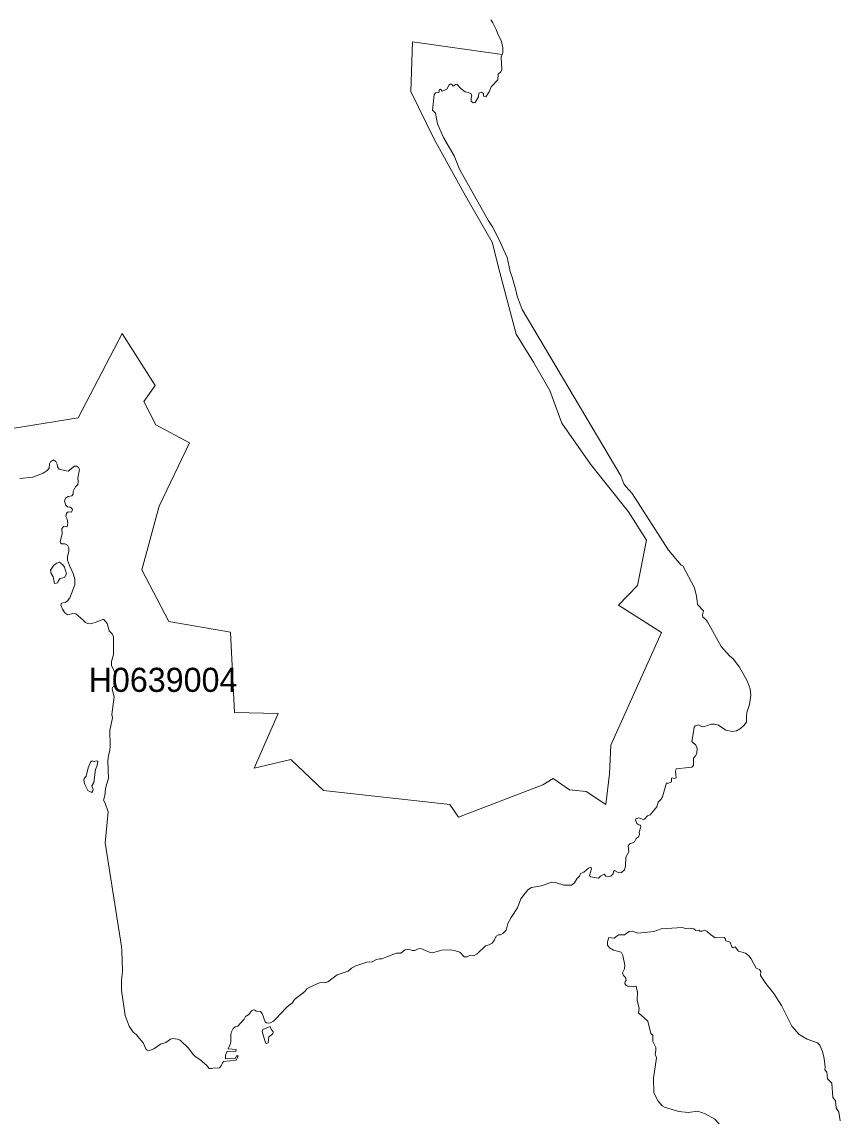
# Model space of a CAD drawing. Extents: x 369010 to 739155, y 6377141 to 6616555.
# Drawn here: x 443226 to 446619, y 6520707 to 6525263 of the extents above; entities that cross this region are included whole.
import ezdxf
from ezdxf.enums import TextEntityAlignment as Align

# ---------------------------------------------------------------- set-up
doc = ezdxf.new("R2010")
doc.units = 0
doc.header["$LTSCALE"] = 40
doc.layers.add('1', color=7, linetype='Continuous', lineweight=13)
doc.layers.add('2', color=7, linetype='Continuous')

msp = doc.modelspace()

# ---------------------------------------------------------------- linework, layer by layer
at = {"layer": '1'}
for points in [[(443133.32, 6523567.17), (443460.03, 6523619.97), (443641.92, 6523970.67), (443778.95, 6523754.36), (443731.62, 6523688.49), (443781.6, 6523591.01), (443921.29, 6523517.19), (443794.84, 6523253.38), (443723.68, 6522989.73), (443835.89, 6522775.57), (444091.59, 6522730.72), (444107.31, 6522398.38), (444289.2, 6522393.25), (444189.07, 6522166.35), (444341.83, 6522203.26), (444476.39, 6522074.16), (445000.87, 6522016.07), (445036.29, 6521963.77), (445386.83, 6522098.33), (445429.03, 6522124.64), (445497.55, 6522077.31), (445566.07, 6522069.36), (445647.66, 6522016.57), (445663.55, 6522143.18), (445668.84, 6522261.84), (445879.2, 6522730.05), (445700.12, 6522843.42), (445779.07, 6522925.18), (445815.98, 6523112.37), (445742.16, 6523231.04), (445584.11, 6523428.81), (445465.94, 6523598.95), (445415.95, 6523733.34), (445347.44, 6523852.01), (445276.27, 6523968.02), (445207.75, 6524223.89), (445176.14, 6524349.01), (445065.42, 6524541.5), (444936.16, 6524776.18), (444838.68, 6524973.96), (444846.46, 6525180.67), (445217.52, 6525128.04), (445220.16, 6525136.65), (445220.99, 6525155.18), (445214.7, 6525182.16), (445198.65, 6525216.75), (445192.69, 6525232.31), (445179.78, 6525259.12), (445171.01, 6525271.37)], [(444949.4, 6524840.07), (444940.96, 6524883.92), (444929.37, 6524897.16), (444935.66, 6524960.55), (444940.96, 6524968.83), (444955.19, 6524970.81), (444957.67, 6524982.56), (444961.98, 6524984.05), (444968.93, 6524975.28), (444978.2, 6524980.58), (444988.29, 6524984.05), (444998.55, 6525001.6), (445002.53, 6525004.91), (445007.32, 6525004.91), (445015.27, 6524996.63), (445024.54, 6525004.08), (445030.33, 6525004.41), (445046.88, 6524987.36), (445064.92, 6524973.3), (445077.66, 6524969.82), (445089.08, 6524964.52), (445092.06, 6524956.25), (445089.08, 6524946.48), (445090.08, 6524933.74), (445098.35, 6524927.45), (445106.13, 6524929.27), (445119.87, 6524951.78), (445120.86, 6524966.84), (445126.16, 6524970.32), (445132.45, 6524971.31), (445141.22, 6524965.52), (445141.22, 6524955.75), (445150.65, 6524951.78), (445163.73, 6524972.8), (445172, 6524993.32), (445199.81, 6525022.62), (445201.3, 6525046.95), (445213.05, 6525056.21), (445216.69, 6525065.98), (445214.2, 6525116.62), (445217.52, 6525128.04), (444846.46, 6525180.67), (444838.68, 6524973.96), (444936.16, 6524776.18), (445065.42, 6524541.5), (445176.14, 6524349.01), (445207.75, 6524223.89), (445276.27, 6523968.02), (445347.44, 6523852.01), (445415.95, 6523733.34), (445465.94, 6523598.95), (445584.11, 6523428.81), (445742.16, 6523231.04), (445815.98, 6523112.37), (445779.07, 6522925.18), (445700.12, 6522843.42), (445879.2, 6522730.05), (445668.84, 6522261.84), (445663.55, 6522143.18), (445647.66, 6522016.57), (445566.07, 6522069.36), (445497.55, 6522077.31), (445429.03, 6522124.64), (445386.83, 6522098.33), (445036.29, 6521963.77), (445000.87, 6522016.07), (444476.39, 6522074.16), (444341.83, 6522203.26), (444189.07, 6522166.35), (444289.2, 6522393.25), (444107.31, 6522398.38), (444091.59, 6522730.72), (443835.89, 6522775.57), (443723.68, 6522989.73), (443794.84, 6523253.38), (443921.29, 6523517.19), (443781.6, 6523591.01), (443731.62, 6523688.49), (443778.95, 6523754.36), (443641.92, 6523970.67), (443460.03, 6523619.97), (443133.32, 6523567.17)], [(445712.7, 6521734.55), (445725.94, 6521744.31), (445730.08, 6521760.04), (445730.58, 6521798.1), (445743.16, 6521820.11), (445741.17, 6521843.95), (445747.62, 6521853.38), (445759.21, 6521856.36), (445767.32, 6521861.82), (445774.11, 6521875.39), (445783.7, 6521882.18), (445788.01, 6521892.27), (445786.02, 6521900.88), (445793.63, 6521923.22), (445791.15, 6521930.5), (445784.37, 6521931.99), (445776.42, 6521937.29), (445770.63, 6521952.85), (445772.12, 6521956.82), (445784.37, 6521960.3), (445803.23, 6521953.84), (445807.7, 6521954.83), (445821.44, 6521968.57), (445832.53, 6521972.87), (445859.34, 6522006.14), (445864.8, 6522025.17), (445876.55, 6522036.43), (445882.51, 6522048.01), (445899.72, 6522106.6), (445905.52, 6522102.63), (445919.75, 6522110.08), (445919.75, 6522125.14), (445923.56, 6522126.63), (445932.82, 6522123.65), (445940.11, 6522126.13), (445937.29, 6522152.45), (445940.11, 6522163.7), (445990.92, 6522169.49), (446003.99, 6522170.49), (446011.44, 6522178.26), (446010.94, 6522208.55), (446020.71, 6522219.31), (446026, 6522230.56), (446026.66, 6522248.6), (446021.37, 6522262.67), (446004.82, 6522277.9), (446010.11, 6522309.18), (446014.58, 6522336.98), (446018.89, 6522342.78), (446032.62, 6522346.25), (446044.87, 6522340.29), (446054.97, 6522337.98), (446084.26, 6522349.56), (446098.49, 6522350.06), (446114.88, 6522344.76), (446145.5, 6522324.74), (446171.31, 6522318.45), (446189.52, 6522321.76), (446207.06, 6522332.02), (446220.63, 6522343.77), (446230.9, 6522357.84), (446231.89, 6522378.86), (446232.88, 6522397.39), (446244.14, 6522431.15), (446249.76, 6522469.72), (446246.29, 6522495.54), (446233.54, 6522529.13), (446202.93, 6522586.23), (446175.62, 6522620.99), (446160.72, 6522633.57), (446126.96, 6522671.14), (446069.86, 6522773.58), (446062.91, 6522784.34), (446049.67, 6522793.61), (446049.17, 6522803.37), (446052.65, 6522819.43), (446027.66, 6522846.4), (446026.83, 6522859.98), (446023.35, 6522880.99), (446015.58, 6522915.58), (445966.75, 6523006.45), (445959.97, 6523009.26), (445907.5, 6523070.83), (445757.72, 6523307), (445731.9, 6523334.31), (445723.13, 6523346.56), (445710.39, 6523379.66), (445300.27, 6524070.14), (445279.91, 6524125.25), (445273.95, 6524155.04), (445260.05, 6524204.7), (445251.28, 6524228.2), (445238.7, 6524286.29), (445205.43, 6524359.44), (445177.63, 6524413.56), (445161.24, 6524438.06), (445040.59, 6524652.71), (445018.91, 6524707.83), (444974.89, 6524783.96), (444949.4, 6524840.07)], [(443217.23, 6523368.4), (443271.85, 6523374.69), (443313.72, 6523390.42), (443330.94, 6523402.5), (443338.71, 6523412.26), (443340.2, 6523429.81), (443344.51, 6523438.25), (443356.75, 6523445.53), (443366.68, 6523438.58), (443372.64, 6523427.49), (443373.97, 6523416.73), (443379.92, 6523407.46), (443409.71, 6523400.68), (443418.49, 6523399.68), (443444.31, 6523419.71), (443452.58, 6523420.54), (443461.35, 6523414.74), (443465.32, 6523406.47), (443457.38, 6523370.39), (443459.86, 6523355.16), (443457.38, 6523343.58), (443447.78, 6523334.31), (443438.84, 6523315.28), (443438.51, 6523303.53), (443433.55, 6523297.24), (443417.99, 6523294.26), (443407.23, 6523286.48), (443402.6, 6523274.23), (443407.73, 6523258.67), (443414.51, 6523250.73), (443425.93, 6523249.9), (443432.39, 6523245.43), (443435.2, 6523240.63), (443431.89, 6523229.38), (443418.16, 6523230.37), (443411.37, 6523224.42), (443408.39, 6523211.34), (443413.85, 6523200.58), (443416.17, 6523185.36), (443414.35, 6523167.81), (443399.12, 6523169.3), (443391.84, 6523160.53), (443393.33, 6523139.51), (443384.06, 6523106.91), (443386.54, 6523101.45), (443390.85, 6523097.14), (443404.09, 6523097.64), (443414.85, 6523092.18), (443420.31, 6523080.59), (443421.3, 6523065.37)], [(443421.3, 6523065.37), (443415.51, 6523044.84), (443415.51, 6523029.29), (443423.29, 6523007.27), (443438.84, 6522975.17), (443445.46, 6522950.67), (443445.46, 6522927.34), (443425.44, 6522873.22), (443415.34, 6522861.46), (443405.58, 6522854.18), (443390.85, 6522851.7), (443387.04, 6522842.93), (443393.83, 6522825.88), (443404.58, 6522811.15), (443417.16, 6522802.88), (443437.69, 6522808.67), (443450.1, 6522806.85), (443478.9, 6522782.85), (443489.65, 6522770.6), (443498.92, 6522766.8), (443510.67, 6522765.31), (443530.2, 6522770.6), (443537.48, 6522774.58), (443561.32, 6522784.34), (443566.28, 6522783.35), (443580.35, 6522766.8), (443587.3, 6522736.01), (443599.22, 6522725.26), (443606, 6522712.68), (443606, 6522638.86), (443598.22, 6522609.24), (443597.73, 6522591.2), (443611.3, 6522565.21), (443612.29, 6522548.66), (443608.49, 6522530.62), (443609.48, 6522506.62), (443601.7, 6522502.82), (443600.21, 6522495.04), (443608.65, 6522462.77), (443599.38, 6522389.61), (443601.37, 6522375.88), (443590.94, 6522322.75), (443592.76, 6522259.36), (443590.94, 6522240.33), (443584.98, 6522219.81), (443581.84, 6522196.3), (443585.31, 6522125.14), (443572.57, 6522082.77), (443569.92, 6522051.98), (443564.46, 6522033.45), (443571.91, 6522021.2), (443583.99, 6521985.62), (443571.41, 6521857.19), (443639.27, 6521426.38), (443639.93, 6521409.99), (443642.58, 6521326.08), (443639.1, 6521284.54), (443638.77, 6521245.98), (443654.33, 6521141.22), (443670.88, 6521095.87), (443687.27, 6521071.54), (443699.51, 6521061.11), (443729.47, 6521026.52), (443739.73, 6521002.19), (443746.18, 6520996.9), (443755.45, 6520995.74), (443773, 6521002.69), (443801.13, 6521022.05), (443823.64, 6521029.17), (443842.51, 6521042.08), (443852.6, 6521045.39), (443871.14, 6521042.24), (443882.73, 6521037.61), (443917.48, 6521005.01), (443935.69, 6520978.19), (443945.29, 6520969.92), (443964.65, 6520957.67), (443991.79, 6520934.34), (444003.21, 6520920.76), (444013.97, 6520920.93), (444024.07, 6520923.91), (444038.8, 6520922.25), (444046.08, 6520924.08), (444052.53, 6520932.18), (444058.16, 6520943.94), (444062.63, 6520949.73), (444114.1, 6520955.19), (444123.04, 6520973.06), (444116.58, 6520973.23), (444110.13, 6520962.64), (444069.91, 6520960.98), (444069.91, 6520976.21), (444077.36, 6520992.43), (444112.94, 6520991.27), (444114.27, 6520999.71), (444081.5, 6521002.03), (444090.6, 6521024.37), (444092.25, 6521033.31), (444092.92, 6521061.28), (444095.73, 6521072.86)], [(444095.73, 6521072.86), (444102.35, 6521086.93), (444110.13, 6521092.89), (444121.38, 6521097.03), (444133.3, 6521108.12), (444148.36, 6521125.82), (444152.99, 6521136.25), (444167.56, 6521145.02), (444178.98, 6521160.08), (444187.25, 6521163.89), (444192.71, 6521162.73), (444197.84, 6521158.1), (444215.39, 6521157.44), (444222.34, 6521148.83), (444235.58, 6521114.9), (444240.71, 6521110.6), (444247.99, 6521108.28), (444257.43, 6521109.61), (444269.34, 6521116.56), (444279.6, 6521126.98), (444322.14, 6521172), (444335.71, 6521184.58), (444346.8, 6521192.19), (444357.06, 6521206.92), (444399.43, 6521240.02), (444407.54, 6521251.28), (444420.28, 6521258.72), (444462.82, 6521277.1), (444481.02, 6521276.76), (444495.42, 6521280.07), (444533.65, 6521309.2), (444578.67, 6521323.93), (444593.57, 6521336.35), (444610.94, 6521346.94), (444656.29, 6521362.5), (444679.46, 6521363.49), (444696.34, 6521373.09), (444708.76, 6521375.4), (444719.02, 6521375.4), (444739.37, 6521383.68), (444779.59, 6521398.58), (444798.13, 6521399.07), (444815.34, 6521412.81), (444831.73, 6521415.46), (444844.8, 6521410.33), (444855.56, 6521410.66), (444869.13, 6521416.78), (444880.88, 6521418.1), (444918.78, 6521402.22), (444929.21, 6521400.56), (444967.27, 6521411.48), (445001.7, 6521413.3), (445020.23, 6521410.82), (445041.75, 6521402.88), (445060.45, 6521383.68), (445073.36, 6521384.18), (445082.13, 6521388.98), (445098.68, 6521388.15), (445114.24, 6521397.09), (445148.17, 6521429.69), (445164.22, 6521433.99), (445176.14, 6521440.94), (445186.23, 6521454.18), (445193.52, 6521469.74), (445203.45, 6521475.2), (445210.56, 6521475.37), (445220.16, 6521480.5), (445234.56, 6521494.57), (445241.18, 6521521.71), (445255.58, 6521547.03), (445281.07, 6521587.42), (445295.47, 6521624.65), (445323.77, 6521662.06), (445340.15, 6521671.82), (445380.37, 6521678.61), (445424.06, 6521693.5), (445442.77, 6521691.52), (445473.88, 6521680.76), (445505.16, 6521681.09), (445518.24, 6521690.69), (445528, 6521707.9), (445539.09, 6521718.66), (445542.4, 6521730.25), (445557.29, 6521734.71), (445575.5, 6521751.93), (445586.26, 6521756.73), (445588.58, 6521748.95), (445579.97, 6521721.31), (445584.6, 6521715.35), (445617.04, 6521710.22), (445626.14, 6521719.32), (445641.7, 6521726.44), (445647.99, 6521718.66), (445658.91, 6521716.67), (445669.01, 6521719.16), (445678.11, 6521728.26), (445679.27, 6521738.52), (445683.91, 6521742.16), (445702.11, 6521731.9), (445712.7, 6521734.55)], [(446619.33, 6520703.79), (446613.87, 6520739.54), (446602.78, 6520756.92), (446600.14, 6520786.71), (446590.04, 6520800.44), (446584.91, 6520859.2), (446567.86, 6520877.9), (446564.22, 6520905.7), (446556.44, 6520914.48), (446557.93, 6520926.06), (446553.46, 6520962.47), (446546.35, 6520991.6), (446535.26, 6521017.42), (446525.33, 6521027.02), (446482.46, 6521042.41), (446449.53, 6521061.77), (446419.57, 6521096.2), (446375.88, 6521181.43), (446344.43, 6521231.25), (446311, 6521273.45), (446289.82, 6521306.22), (446290.48, 6521322.94), (446284.85, 6521330.88), (446271.11, 6521337.67), (446250.76, 6521375.4), (446240.66, 6521388.15), (446226.76, 6521399.4), (446198.79, 6521406.85), (446184.39, 6521424.89), (446175.62, 6521421.75), (446170.98, 6521425.22), (446163.7, 6521444.92), (446146.16, 6521450.21), (446143.18, 6521459.65), (446138.38, 6521463.62), (446101.64, 6521463.29), (446081.61, 6521476.36), (446068.87, 6521489.6), (446056.79, 6521494.4), (446048.01, 6521490.43), (446038.25, 6521490.43), (446033.62, 6521494.73), (446021.2, 6521493.41), (446013.26, 6521499.7), (445996.21, 6521502.68), (445977.18, 6521501.02), (445966.09, 6521505.66), (445877.88, 6521499.7), (445847.09, 6521488.61), (445780.89, 6521481.66), (445757.89, 6521490.43), (445744.48, 6521489.44), (445724.78, 6521475.7), (445700.79, 6521475.7), (445681.92, 6521461.63), (445660.57, 6521463.62), (445654.94, 6521446.24), (445655.27, 6521432.83), (445663.22, 6521421.25), (445679.44, 6521411.82), (445711.21, 6521403.04), (445718.66, 6521389.14), (445727.27, 6521349.25), (445724.95, 6521334.86), (445717.34, 6521318.14), (445720.81, 6521306.55), (445729.09, 6521298.78), (445731.74, 6521285.87), (445727.76, 6521281.73), (445727.43, 6521273.79), (445732.73, 6521265.68), (445743.49, 6521260.71), (445753.91, 6521262.37), (445763.18, 6521259.39), (445773.28, 6521262.37), (445778.9, 6521236.71), (445777.91, 6521203.28), (445786.85, 6521171.5), (445783.37, 6521151.48), (445821.94, 6521117.71), (445835.01, 6521066.57), (445842.46, 6521059.13), (445842.46, 6521032.48), (445854.87, 6521007.32), (445855.86, 6520995.57), (445852.22, 6520980.35), (445858.68, 6520964.29), (445845.6, 6520880.71), (445847.09, 6520819.15), (445865.13, 6520784.72), (445881.85, 6520765.69), (445891.78, 6520760.72), (445950.53, 6520742.02), (445989.92, 6520737.55), (446029.64, 6520744.01), (446060.43, 6520733.25), (446099.65, 6520709.91), (446118.68, 6520690.55)]]:
    msp.add_lwpolyline(points, dxfattribs=at)
for points in [[(443382.41, 6523021.01), (443371.15, 6523018.03), (443358.91, 6523009.26), (443344.84, 6522988.24), (443347.65, 6522975.17), (443355.43, 6522960.44), (443361.39, 6522932.63), (443374.46, 6522936.11), (443377.94, 6522945.38), (443385.22, 6522953.15), (443403.26, 6522958.12), (443410.54, 6522972.68), (443402.76, 6523000.49), (443395.98, 6523010.25)], [(443516.96, 6522197.3), (443511.17, 6522191.5), (443501.4, 6522168.5), (443492.63, 6522133.91), (443484.36, 6522124.64), (443482.87, 6522114.38), (443486.67, 6522099.32), (443499.91, 6522074.82), (443515.47, 6522066.55), (443519.44, 6522070.52), (443520.93, 6522078.8), (443515.47, 6522093.36), (443523.75, 6522107.1), (443531.19, 6522161.22), (443538.48, 6522177.77), (443540.46, 6522195.48), (443535.99, 6522197.79), (443526.23, 6522194.98)], [(444256.27, 6521094.71), (444225.48, 6521082.46), (444222.51, 6521073.53), (444236.57, 6521027.35), (444241.21, 6521024.04), (444247, 6521027.02), (444250.31, 6521052.01), (444266.69, 6521064.09), (444268.68, 6521072.2), (444259.58, 6521084.12)]]:
    msp.add_lwpolyline(points, close=True, dxfattribs=at)

# ---------------------------------------------------------------- texts
at = {"layer": '2'}
msp.add_text('H0639004', height=100, dxfattribs=at).set_placement((443811.32, 6522483.33), align=Align.CENTER)

doc.saveas('drawing.dxf')
